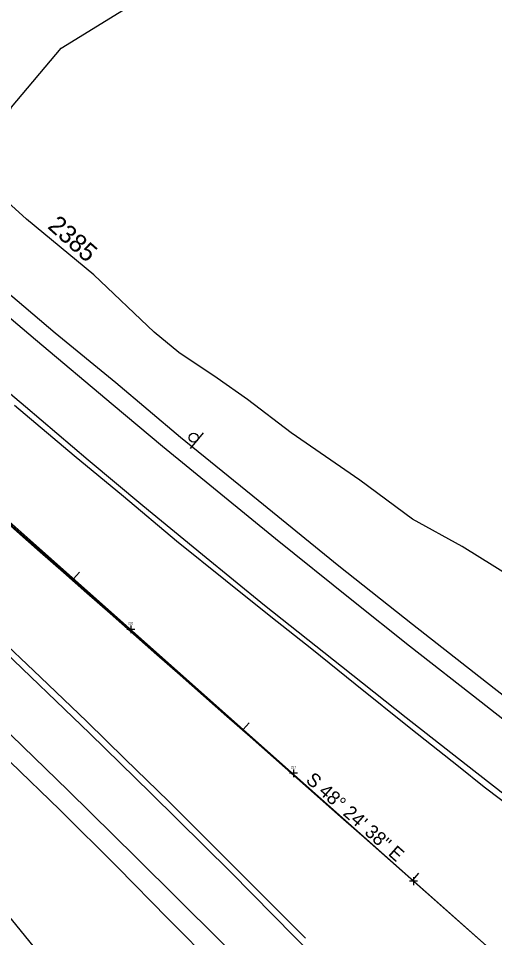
# Model space of a CAD drawing. Extents: x 2076109 to 2080761, y 592812 to 596750.
# Drawn here: x 2077518.8 to 2077728.7, y 595417.5 to 595822.6 of the extents above; entities that cross this region are included whole.
import ezdxf

# ---------------------------------------------------------------- set-up
doc = ezdxf.new("R2010")
doc.units = 0
for name, color, linetype in [('Default', 7, 'Continuous'), ('RD_EX_BldgApp', 7, 'Continuous'), ('RD_EX_Fence_ChLk', 7, 'Continuous'), ('RD_EX_Misc', 7, 'Continuous'), ('RD_EX_Road', 7, 'Continuous'), ('RD_EX_VEG', 7, 'Continuous'), ('RD_HC_Cl', 7, 'Continuous'), ('RD_HC_Data', 7, 'Continuous'), ('RD_HC_Data_Tic', 7, 'Continuous'), ('RD_HC_TX_Sta50', 7, 'Continuous')]:
    doc.layers.add(name, color=color, linetype=linetype)

msp = doc.modelspace()

# ---------------------------------------------------------------- linework, layer by layer
at = {"layer": 'Default'}
for p, q in [((2077364.31, 595733.06), (2078453.96, 594769.07)), ((2077364.31, 595733.06), (2078453.96, 594769.07)), ((2077404.89, 595698.18), (2078420.27, 594797.03)), ((2077404.89, 595698.18), (2078420.27, 594797.03)), ((2077570.07, 595553.33), (2077566.57, 595553.33)), ((2077570.07, 595553.33), (2077566.57, 595553.33)), ((2077568.32, 595555.08), (2077568.32, 595551.58)), ((2077568.32, 595555.08), (2077568.32, 595551.58)), ((2077641.81, 595489.88), (2077638.31, 595489.88)), ((2077641.81, 595489.88), (2077638.31, 595489.88)), ((2077640.06, 595491.63), (2077640.06, 595488.13)), ((2077640.06, 595491.63), (2077640.06, 595488.13)), ((2077692.91, 595444.11), (2077692.91, 595440.61)), ((2077692.91, 595444.11), (2077692.91, 595440.61)), ((2077694.66, 595442.36), (2077691.16, 595442.36)), ((2077694.66, 595442.36), (2077691.16, 595442.36))]:
    msp.add_line(p, q, dxfattribs=at)
msp.add_arc((2035586.7, 547847.96), 63546.51, 48.5011873, 49.2923126, dxfattribs=at)
msp.add_arc((2035586.7, 547847.96), 63546.51, 48.5011873, 49.2923126, dxfattribs=at)
at = {"layer": 'RD_EX_BldgApp'}
msp.add_line((2077594.57, 595633.07), (2077600.43, 595639.89), dxfattribs=at)
msp.add_line((2077594.57, 595633.07), (2077600.43, 595639.89), dxfattribs=at)
msp.add_circle((2077595.98, 595637.81), 2, dxfattribs=at)
msp.add_circle((2077595.98, 595637.81), 2, dxfattribs=at)
at = {"layer": 'RD_EX_Fence_ChLk'}
msp.add_lwpolyline([(2077335.75, 595618.26), (2077356.53, 595599.53), (2077407.57, 595552.05), (2077423.46, 595535.25), (2077447.78, 595507.68), (2077494.27, 595451.57), (2077527.1, 595411.56), (2077548.1, 595385.61), (2077582.49, 595344.46)], dxfattribs=at)
msp.add_lwpolyline([(2077335.75, 595618.26), (2077356.53, 595599.53), (2077407.57, 595552.05), (2077423.46, 595535.25), (2077447.78, 595507.68), (2077494.27, 595451.57), (2077527.1, 595411.56), (2077548.1, 595385.61), (2077582.49, 595344.46)], dxfattribs=at)
at = {"layer": 'RD_EX_Misc'}
for points in [[(2077949.74, 595346.22), (2077917.12, 595371.24), (2077886.25, 595394.66), (2077855.54, 595418.26), (2077826.17, 595440.63), (2077793.37, 595466.01), (2077761.67, 595490.62), (2077722.71, 595521.26), (2077691.23, 595545.97), (2077665.74, 595566.25), (2077632.03, 595593.21), (2077582.35, 595633.88), (2077560.53, 595652.07), (2077526.26, 595680.98), (2077495.89, 595706.68), (2077469.6, 595728.93), (2077440.39, 595753.88), (2077413.8, 595776.66), (2077390.58, 595796.7)], [(2077949.74, 595346.22), (2077917.12, 595371.24), (2077886.25, 595394.66), (2077855.54, 595418.26), (2077826.17, 595440.63), (2077793.37, 595466.01), (2077761.67, 595490.62), (2077722.71, 595521.26), (2077691.23, 595545.97), (2077665.74, 595566.25), (2077632.03, 595593.21), (2077582.35, 595633.88), (2077560.53, 595652.07), (2077526.26, 595680.98), (2077495.89, 595706.68), (2077469.6, 595728.93), (2077440.39, 595753.88), (2077413.8, 595776.66), (2077390.58, 595796.7)], [(2077362.93, 595786.89), (2077392.15, 595761.97), (2077424.77, 595734), (2077441.81, 595719.44), (2077465.76, 595699.03), (2077496.26, 595672.94), (2077521.85, 595651.48), (2077549.58, 595628.1), (2077573.59, 595607.87), (2077599.85, 595586.33), (2077627.21, 595563.92), (2077661.18, 595537.05), (2077689.72, 595514.51), (2077716.09, 595493.76), (2077749.65, 595467.6), (2077783.36, 595441.51), (2077815.88, 595416.61), (2077850.74, 595389.82), (2077878.87, 595368.26), (2077915.16, 595340.49), (2077948.94, 595314.49)], [(2077362.93, 595786.89), (2077392.15, 595761.97), (2077424.77, 595734), (2077441.81, 595719.44), (2077465.76, 595699.03), (2077496.26, 595672.94), (2077521.85, 595651.48), (2077549.58, 595628.1), (2077573.59, 595607.87), (2077599.85, 595586.33), (2077627.21, 595563.92), (2077661.18, 595537.05), (2077689.72, 595514.51), (2077716.09, 595493.76), (2077749.65, 595467.6), (2077783.36, 595441.51), (2077815.88, 595416.61), (2077850.74, 595389.82), (2077878.87, 595368.26), (2077915.16, 595340.49), (2077948.94, 595314.49)], [(2077850.7, 595201.63), (2077820.53, 595232.8), (2077790.22, 595263.88), (2077762.8, 595291.76), (2077736.42, 595318.96), (2077709.92, 595346.36), (2077678.72, 595378.46), (2077649.91, 595408.22), (2077612.46, 595446.3), (2077577.19, 595481.07), (2077550.3, 595507.41), (2077509.12, 595546.77), (2077481.37, 595572.73), (2077443, 595608.1), (2077400.67, 595646.86), (2077373.88, 595670.82), (2077334.03, 595706.37), (2077304.56, 595732)], [(2077850.7, 595201.63), (2077820.53, 595232.8), (2077790.22, 595263.88), (2077762.8, 595291.76), (2077736.42, 595318.96), (2077709.92, 595346.36), (2077678.72, 595378.46), (2077649.91, 595408.22), (2077612.46, 595446.3), (2077577.19, 595481.07), (2077550.3, 595507.41), (2077509.12, 595546.77), (2077481.37, 595572.73), (2077443, 595608.1), (2077400.67, 595646.86), (2077373.88, 595670.82), (2077334.03, 595706.37), (2077304.56, 595732)], [(2077812.69, 595205.74), (2077779.15, 595240.73), (2077743.86, 595277.34), (2077707.16, 595314.93), (2077677.78, 595345.17), (2077641.95, 595381.51), (2077607.57, 595416.21), (2077570.67, 595452.82), (2077540.71, 595482.36), (2077500.4, 595521.29), (2077469.88, 595550.44), (2077431.8, 595585.6), (2077401.7, 595612.91), (2077373.73, 595637.96), (2077342.22, 595666.06), (2077323.28, 595683.05), (2077307.69, 595696.83), (2077294.47, 595708.58)], [(2077812.69, 595205.74), (2077779.15, 595240.73), (2077743.86, 595277.34), (2077707.16, 595314.93), (2077677.78, 595345.17), (2077641.95, 595381.51), (2077607.57, 595416.21), (2077570.67, 595452.82), (2077540.71, 595482.36), (2077500.4, 595521.29), (2077469.88, 595550.44), (2077431.8, 595585.6), (2077401.7, 595612.91), (2077373.73, 595637.96), (2077342.22, 595666.06), (2077323.28, 595683.05), (2077307.69, 595696.83), (2077294.47, 595708.58)]]:
    msp.add_lwpolyline(points, dxfattribs=at)
at = {"layer": 'RD_EX_Road'}
for points in [[(2077753.88, 595507.5), (2077725.13, 595529.95), (2077692.51, 595555.53), (2077660, 595581.25), (2077624.46, 595610.18), (2077590.24, 595637.95), (2077561.78, 595661.94), (2077534.99, 595683.83), (2077518.29, 595698.14), (2077492.56, 595719.65), (2077469.48, 595739.08), (2077464.38, 595743.91), (2077465.16, 595745.87), (2077471.12, 595754.97), (2077455.17, 595766.04), (2077441.89, 595773.92), (2077435.65, 595777.78), (2077425.27, 595787.12), (2077414.92, 595795.42), (2077405.25, 595804.28)], [(2077753.88, 595507.5), (2077725.13, 595529.95), (2077692.51, 595555.53), (2077660, 595581.25), (2077624.46, 595610.18), (2077590.24, 595637.95), (2077561.78, 595661.94), (2077534.99, 595683.83), (2077518.29, 595698.14), (2077492.56, 595719.65), (2077469.48, 595739.08), (2077464.38, 595743.91), (2077465.16, 595745.87), (2077471.12, 595754.97), (2077455.17, 595766.04), (2077441.89, 595773.92), (2077435.65, 595777.78), (2077425.27, 595787.12), (2077414.92, 595795.42), (2077405.25, 595804.28)], [(2077277.58, 595711.76), (2077294.44, 595696.44), (2077316.48, 595676.87), (2077339.86, 595656.39), (2077363.23, 595635.78), (2077381.85, 595618.74), (2077401.46, 595601.04), (2077426.38, 595578.58), (2077449.29, 595557.26), (2077472.1, 595535.89), (2077492.72, 595516.55), (2077515.1, 595494.99), (2077537.08, 595473.82), (2077562.41, 595448.47), (2077584.67, 595425.87), (2077605.91, 595404.49), (2077629.68, 595380.24), (2077656.48, 595352.83), (2077679.73, 595328.95), (2077700.7, 595307.57), (2077723.07, 595284.36), (2077743.1, 595263.78)], [(2077277.58, 595711.76), (2077294.44, 595696.44), (2077316.48, 595676.87), (2077339.86, 595656.39), (2077363.23, 595635.78), (2077381.85, 595618.74), (2077401.46, 595601.04), (2077426.38, 595578.58), (2077449.29, 595557.26), (2077472.1, 595535.89), (2077492.72, 595516.55), (2077515.1, 595494.99), (2077537.08, 595473.82), (2077562.41, 595448.47), (2077584.67, 595425.87), (2077605.91, 595404.49), (2077629.68, 595380.24), (2077656.48, 595352.83), (2077679.73, 595328.95), (2077700.7, 595307.57), (2077723.07, 595284.36), (2077743.1, 595263.78)], [(2077517.08, 595652.15), (2077543.34, 595629.88), (2077565.07, 595611.96), (2077588.48, 595592.38), (2077609.99, 595575.05), (2077629.97, 595558.97), (2077648.13, 595544.8), (2077667.21, 595529.38), (2077691.78, 595509.7), (2077712.81, 595493.06), (2077724.01, 595483.86), (2077746.81, 595466.67)], [(2077517.08, 595652.15), (2077543.34, 595629.88), (2077565.07, 595611.96), (2077588.48, 595592.38), (2077609.99, 595575.05), (2077629.97, 595558.97), (2077648.13, 595544.8), (2077667.21, 595529.38), (2077691.78, 595509.7), (2077712.81, 595493.06), (2077724.01, 595483.86), (2077746.81, 595466.67)], [(2077645.25, 595417.29), (2077624.4, 595438.11), (2077608.43, 595454.05), (2077584.89, 595477.66), (2077565.88, 595496.09), (2077548.93, 595512.77), (2077528.44, 595532.32), (2077507.93, 595551.7)], [(2077645.25, 595417.29), (2077624.4, 595438.11), (2077608.43, 595454.05), (2077584.89, 595477.66), (2077565.88, 595496.09), (2077548.93, 595512.77), (2077528.44, 595532.32), (2077507.93, 595551.7)]]:
    msp.add_lwpolyline(points, dxfattribs=at)
at = {"layer": 'RD_EX_VEG'}
msp.add_lwpolyline([(2077743.14, 595571.92), (2077714.37, 595589.83), (2077692.45, 595601.95), (2077669.32, 595619.14), (2077639, 595640.01), (2077619.76, 595654.64), (2077606.34, 595663.97), (2077589.56, 595675.42), (2077578.67, 595684.27), (2077551.96, 595709.63), (2077522.34, 595734.14), (2077510.92, 595744.54), (2077504.79, 595753.59), (2077507.34, 595764.85), (2077515.75, 595783.48), (2077537.58, 595809.49), (2077586.06, 595839.41)], dxfattribs=at)
msp.add_lwpolyline([(2077743.14, 595571.92), (2077714.37, 595589.83), (2077692.45, 595601.95), (2077669.32, 595619.14), (2077639, 595640.01), (2077619.76, 595654.64), (2077606.34, 595663.97), (2077589.56, 595675.42), (2077578.67, 595684.27), (2077551.96, 595709.63), (2077522.34, 595734.14), (2077510.92, 595744.54), (2077504.79, 595753.59), (2077507.34, 595764.85), (2077515.75, 595783.48), (2077537.58, 595809.49), (2077586.06, 595839.41)], dxfattribs=at)
at = {"layer": 'RD_HC_Cl'}
msp.add_line((2077404.89, 595698.18), (2077928.38, 595233.58), dxfattribs=at)
msp.add_line((2077404.89, 595698.18), (2077928.38, 595233.58), dxfattribs=at)
at = {"layer": 'RD_HC_Data_Tic'}
for p, q in [((2077543.04, 595575.57), (2077545.7, 595578.57)), ((2077543.04, 595575.57), (2077545.7, 595578.57)), ((2077617.84, 595509.2), (2077620.49, 595512.19)), ((2077617.84, 595509.2), (2077620.49, 595512.19)), ((2077692.63, 595442.82), (2077695.28, 595445.81)), ((2077692.63, 595442.82), (2077695.28, 595445.81))]:
    msp.add_line(p, q, dxfattribs=at)

# ---------------------------------------------------------------- texts
at = {"layer": 'Default'}
for s, p in [('226', (2077567.11, 595555.53)), ('226', (2077567.11, 595555.53)), ('227', (2077638.88, 595492.08)), ('227', (2077638.88, 595492.08))]:
    msp.add_text(s, height=1, dxfattribs=at).set_placement(p)
at = {"layer": 'RD_HC_Data'}
msp.add_text('S 48%%d 24\' 38" E', height=6, rotation=318.4105, dxfattribs=at).set_placement((2077645.06, 595486.37))
msp.add_text('S 48%%d 24\' 38" E', height=6, rotation=318.4105, dxfattribs=at).set_placement((2077645.06, 595486.37))
at = {"layer": 'RD_HC_TX_Sta50'}
msp.add_text('2385', height=8, rotation=318.4105, dxfattribs=at).set_placement((2077531.24, 595730.45))
msp.add_text('2385', height=8, rotation=318.4105, dxfattribs=at).set_placement((2077531.24, 595730.45))

doc.saveas('drawing.dxf')
